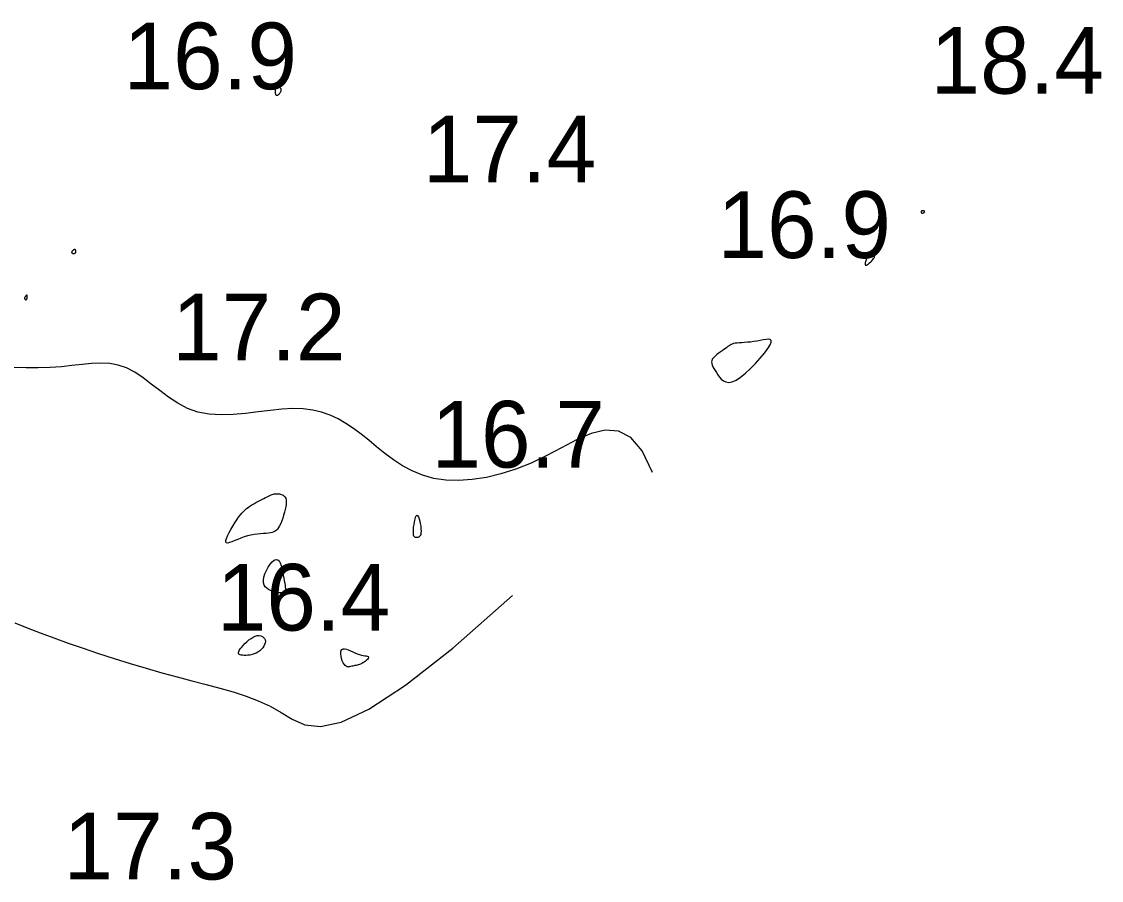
# Model space of a CAD drawing. Extents: x 3040093 to 3056816, y 408076 to 509144.
# Drawn here: x 3045566.4 to 3045647.4, y 433759.6 to 433824 of the extents above; entities that cross this region are included whole.
import ezdxf

# ---------------------------------------------------------------- set-up
doc = ezdxf.new("R2010")
doc.units = 0
doc.layers.add('V-CHAN-CONT-EL17', color=7, linetype='Continuous')
doc.layers.add('V-TOPO-SOUN-0610', color=7, linetype='Continuous')

msp = doc.modelspace()

# ---------------------------------------------------------------- linework, layer by layer
at = {"layer": 'V-CHAN-CONT-EL17'}
for points in [[(3045585.594, 433818.512), (3045585.634, 433818.526), (3045585.676, 433818.551), (3045585.719, 433818.583), (3045585.76, 433818.621), (3045585.799, 433818.664), (3045585.833, 433818.709), (3045585.861, 433818.754), (3045585.883, 433818.798), (3045585.896, 433818.841), (3045585.903, 433818.882), (3045585.903, 433818.921), (3045585.897, 433818.957), (3045585.884, 433818.991), (3045585.864, 433819.021), (3045585.839, 433819.049), (3045585.809, 433819.073), (3045585.774, 433819.093), (3045585.736, 433819.108), (3045585.697, 433819.119), (3045585.657, 433819.124), (3045585.618, 433819.124), (3045585.581, 433819.117), (3045585.548, 433819.104), (3045585.519, 433819.084), (3045585.495, 433819.057), (3045585.476, 433819.025), (3045585.46, 433818.988), (3045585.449, 433818.946), (3045585.441, 433818.901), (3045585.436, 433818.853), (3045585.435, 433818.803), (3045585.437, 433818.752), (3045585.442, 433818.701), (3045585.451, 433818.653), (3045585.463, 433818.608), (3045585.48, 433818.57), (3045585.501, 433818.539), (3045585.527, 433818.518), (3045585.558, 433818.509)], [(3045633.912, 433809.712), (3045633.922, 433809.698), (3045633.935, 433809.686), (3045633.95, 433809.675), (3045633.966, 433809.666), (3045633.984, 433809.661), (3045634.003, 433809.659), (3045634.023, 433809.66), (3045634.043, 433809.666), (3045634.063, 433809.676), (3045634.082, 433809.688), (3045634.1, 433809.703), (3045634.116, 433809.718), (3045634.13, 433809.734), (3045634.142, 433809.75), (3045634.151, 433809.765), (3045634.155, 433809.778), (3045634.157, 433809.79), (3045634.155, 433809.8), (3045634.15, 433809.809), (3045634.141, 433809.816), (3045634.131, 433809.822), (3045634.117, 433809.828), (3045634.101, 433809.833), (3045634.083, 433809.837), (3045634.063, 433809.84), (3045634.043, 433809.843), (3045634.021, 433809.844), (3045634, 433809.844), (3045633.98, 433809.842), (3045633.961, 433809.838), (3045633.944, 433809.832), (3045633.93, 433809.823), (3045633.918, 433809.813), (3045633.909, 433809.801), (3045633.902, 433809.787), (3045633.898, 433809.773), (3045633.897, 433809.758), (3045633.899, 433809.743), (3045633.904, 433809.727)], [(3045570.216, 433806.663), (3045570.242, 433806.653), (3045570.271, 433806.646), (3045570.304, 433806.641), (3045570.338, 433806.64), (3045570.371, 433806.642), (3045570.402, 433806.647), (3045570.429, 433806.654), (3045570.451, 433806.664), (3045570.468, 433806.676), (3045570.48, 433806.691), (3045570.489, 433806.708), (3045570.495, 433806.726), (3045570.498, 433806.746), (3045570.499, 433806.767), (3045570.499, 433806.79), (3045570.498, 433806.813), (3045570.495, 433806.836), (3045570.491, 433806.858), (3045570.486, 433806.879), (3045570.478, 433806.898), (3045570.469, 433806.914), (3045570.456, 433806.926), (3045570.441, 433806.934), (3045570.423, 433806.937), (3045570.402, 433806.935), (3045570.38, 433806.929), (3045570.356, 433806.919), (3045570.331, 433806.905), (3045570.306, 433806.889), (3045570.281, 433806.87), (3045570.258, 433806.85), (3045570.237, 433806.827), (3045570.217, 433806.804), (3045570.202, 433806.78), (3045570.19, 433806.756), (3045570.183, 433806.734), (3045570.181, 433806.712), (3045570.186, 433806.693), (3045570.197, 433806.677)], [(3045629.768, 433806.167), (3045629.739, 433806.089), (3045629.715, 433806.009), (3045629.697, 433805.932), (3045629.69, 433805.864), (3045629.694, 433805.808), (3045629.714, 433805.771), (3045629.75, 433805.758), (3045629.804, 433805.771), (3045629.874, 433805.808), (3045629.953, 433805.864), (3045630.037, 433805.934), (3045630.121, 433806.013), (3045630.201, 433806.095), (3045630.272, 433806.176), (3045630.329, 433806.251), (3045630.367, 433806.316), (3045630.39, 433806.371), (3045630.397, 433806.416), (3045630.393, 433806.452), (3045630.379, 433806.481), (3045630.358, 433806.503), (3045630.332, 433806.518), (3045630.303, 433806.529), (3045630.273, 433806.534), (3045630.242, 433806.536), (3045630.211, 433806.534), (3045630.18, 433806.529), (3045630.149, 433806.522), (3045630.117, 433806.512), (3045630.086, 433806.501), (3045630.054, 433806.488), (3045630.023, 433806.475), (3045629.991, 433806.459), (3045629.959, 433806.44), (3045629.927, 433806.415), (3045629.896, 433806.384), (3045629.864, 433806.346), (3045629.832, 433806.297), (3045629.8, 433806.238)], [(3045566.767, 433803.164), (3045566.781, 433803.171), (3045566.793, 433803.183), (3045566.805, 433803.199), (3045566.815, 433803.219), (3045566.824, 433803.242), (3045566.832, 433803.269), (3045566.839, 433803.299), (3045566.845, 433803.331), (3045566.849, 433803.364), (3045566.852, 433803.397), (3045566.853, 433803.428), (3045566.852, 433803.457), (3045566.849, 433803.482), (3045566.843, 433803.502), (3045566.835, 433803.515), (3045566.825, 433803.52), (3045566.812, 433803.518), (3045566.797, 433803.511), (3045566.781, 433803.499), (3045566.764, 433803.483), (3045566.746, 433803.464), (3045566.729, 433803.444), (3045566.713, 433803.423), (3045566.697, 433803.403), (3045566.683, 433803.384), (3045566.671, 433803.364), (3045566.661, 433803.345), (3045566.654, 433803.326), (3045566.649, 433803.307), (3045566.648, 433803.288), (3045566.65, 433803.269), (3045566.656, 433803.249), (3045566.665, 433803.23), (3045566.676, 433803.212), (3045566.69, 433803.196), (3045566.705, 433803.182), (3045566.721, 433803.171), (3045566.737, 433803.164), (3045566.752, 433803.161)], [(3045620.355, 433797.36), (3045620.725, 433797.658), (3045621.106, 433798.01), (3045621.482, 433798.393), (3045621.833, 433798.784), (3045622.143, 433799.161), (3045622.393, 433799.501), (3045622.565, 433799.78), (3045622.647, 433799.982), (3045622.646, 433800.112), (3045622.574, 433800.184), (3045622.443, 433800.207), (3045622.265, 433800.196), (3045622.053, 433800.16), (3045621.82, 433800.112), (3045621.576, 433800.065), (3045621.334, 433800.027), (3045621.096, 433799.998), (3045620.867, 433799.977), (3045620.65, 433799.961), (3045620.446, 433799.947), (3045620.259, 433799.935), (3045620.093, 433799.92), (3045619.949, 433799.902), (3045619.829, 433799.878), (3045619.729, 433799.847), (3045619.643, 433799.81), (3045619.566, 433799.765), (3045619.491, 433799.713), (3045619.412, 433799.654), (3045619.324, 433799.586), (3045619.222, 433799.511), (3045619.1, 433799.427), (3045618.964, 433799.336), (3045618.821, 433799.238), (3045618.678, 433799.136), (3045618.541, 433799.031), (3045618.417, 433798.923), (3045618.314, 433798.814), (3045618.237, 433798.706), (3045618.193, 433798.598), (3045618.179, 433798.49), (3045618.193, 433798.379), (3045618.23, 433798.263), (3045618.287, 433798.14), (3045618.362, 433798.009), (3045618.449, 433797.866), (3045618.547, 433797.709), (3045618.654, 433797.541), (3045618.772, 433797.371), (3045618.907, 433797.215), (3045619.064, 433797.086), (3045619.248, 433797), (3045619.465, 433796.971), (3045619.719, 433797.012), (3045620.015, 433797.139)], [(3045581.743, 433785.102), (3045581.79, 433785.267), (3045581.875, 433785.469), (3045581.988, 433785.698), (3045582.123, 433785.942), (3045582.271, 433786.19), (3045582.422, 433786.43), (3045582.569, 433786.652), (3045582.706, 433786.846), (3045582.833, 433787.014), (3045582.954, 433787.16), (3045583.07, 433787.287), (3045583.186, 433787.399), (3045583.304, 433787.5), (3045583.427, 433787.593), (3045583.558, 433787.683), (3045583.698, 433787.772), (3045583.847, 433787.86), (3045584, 433787.947), (3045584.155, 433788.032), (3045584.308, 433788.113), (3045584.458, 433788.189), (3045584.599, 433788.261), (3045584.731, 433788.327), (3045584.849, 433788.386), (3045584.956, 433788.438), (3045585.053, 433788.484), (3045585.143, 433788.523), (3045585.226, 433788.555), (3045585.305, 433788.581), (3045585.381, 433788.6), (3045585.457, 433788.613), (3045585.535, 433788.62), (3045585.612, 433788.621), (3045585.69, 433788.616), (3045585.766, 433788.605), (3045585.841, 433788.588), (3045585.913, 433788.566), (3045585.982, 433788.538), (3045586.046, 433788.505), (3045586.106, 433788.467), (3045586.159, 433788.42), (3045586.204, 433788.363), (3045586.241, 433788.292), (3045586.267, 433788.205), (3045586.281, 433788.098), (3045586.282, 433787.97), (3045586.269, 433787.817), (3045586.241, 433787.638), (3045586.199, 433787.439), (3045586.145, 433787.226), (3045586.082, 433787.008), (3045586.013, 433786.791), (3045585.938, 433786.582), (3045585.861, 433786.39), (3045585.783, 433786.22), (3045585.705, 433786.078), (3045585.627, 433785.964), (3045585.543, 433785.873), (3045585.452, 433785.803), (3045585.349, 433785.749), (3045585.232, 433785.709), (3045585.098, 433785.68), (3045584.942, 433785.657), (3045584.764, 433785.639), (3045584.566, 433785.621), (3045584.35, 433785.602), (3045584.12, 433785.577), (3045583.879, 433785.546), (3045583.631, 433785.504), (3045583.379, 433785.449), (3045583.126, 433785.378), (3045582.876, 433785.291), (3045582.635, 433785.194), (3045582.41, 433785.099), (3045582.207, 433785.015), (3045582.032, 433784.952), (3045581.892, 433784.92), (3045581.793, 433784.928), (3045581.742, 433784.986)], [(3045595.818, 433785.913), (3045595.834, 433786.11), (3045595.86, 433786.317), (3045595.894, 433786.519), (3045595.935, 433786.703), (3045595.981, 433786.854), (3045596.031, 433786.957), (3045596.084, 433786.999), (3045596.138, 433786.97), (3045596.192, 433786.879), (3045596.244, 433786.74), (3045596.29, 433786.567), (3045596.33, 433786.374), (3045596.361, 433786.174), (3045596.381, 433785.981), (3045596.388, 433785.81), (3045596.38, 433785.671), (3045596.36, 433785.563), (3045596.329, 433785.481), (3045596.289, 433785.423), (3045596.242, 433785.383), (3045596.19, 433785.358), (3045596.136, 433785.343), (3045596.082, 433785.335), (3045596.029, 433785.33), (3045595.979, 433785.332), (3045595.933, 433785.346), (3045595.893, 433785.375), (3045595.859, 433785.425), (3045595.834, 433785.499), (3045595.817, 433785.603), (3045595.812, 433785.74)], [(3045585.24, 433781.312), (3045585.09, 433781.367), (3045584.946, 433781.436), (3045584.814, 433781.523), (3045584.702, 433781.632), (3045584.617, 433781.766), (3045584.567, 433781.929), (3045584.559, 433782.124), (3045584.598, 433782.353), (3045584.678, 433782.603), (3045584.79, 433782.858), (3045584.925, 433783.105), (3045585.075, 433783.327), (3045585.23, 433783.509), (3045585.382, 433783.636), (3045585.522, 433783.693), (3045585.643, 433783.669), (3045585.745, 433783.574), (3045585.831, 433783.421), (3045585.903, 433783.225), (3045585.963, 433782.999), (3045586.014, 433782.757), (3045586.057, 433782.515), (3045586.096, 433782.284), (3045586.131, 433782.077), (3045586.162, 433781.896), (3045586.187, 433781.738), (3045586.204, 433781.603), (3045586.212, 433781.488), (3045586.208, 433781.394), (3045586.191, 433781.318), (3045586.16, 433781.26), (3045586.112, 433781.217), (3045586.049, 433781.189), (3045585.97, 433781.175), (3045585.878, 433781.173), (3045585.773, 433781.183), (3045585.656, 433781.202), (3045585.527, 433781.231), (3045585.388, 433781.268)], [(3045582.922, 433777.093), (3045583.039, 433777.23), (3045583.173, 433777.373), (3045583.32, 433777.515), (3045583.475, 433777.649), (3045583.636, 433777.768), (3045583.797, 433777.865), (3045583.955, 433777.935), (3045584.106, 433777.97), (3045584.246, 433777.975), (3045584.373, 433777.951), (3045584.484, 433777.903), (3045584.575, 433777.834), (3045584.645, 433777.747), (3045584.691, 433777.647), (3045584.709, 433777.536), (3045584.697, 433777.419), (3045584.658, 433777.298), (3045584.595, 433777.177), (3045584.509, 433777.057), (3045584.406, 433776.943), (3045584.286, 433776.838), (3045584.154, 433776.743), (3045584.012, 433776.663), (3045583.863, 433776.599), (3045583.711, 433776.551), (3045583.558, 433776.517), (3045583.408, 433776.496), (3045583.265, 433776.486), (3045583.131, 433776.486), (3045583.01, 433776.494), (3045582.906, 433776.509), (3045582.82, 433776.53), (3045582.754, 433776.557), (3045582.71, 433776.594), (3045582.687, 433776.641), (3045582.686, 433776.7), (3045582.709, 433776.773), (3045582.756, 433776.862), (3045582.827, 433776.969)], [(3045590.542, 433776.983), (3045590.653, 433776.983), (3045590.785, 433776.951), (3045590.934, 433776.896), (3045591.095, 433776.826), (3045591.263, 433776.749), (3045591.434, 433776.672), (3045591.602, 433776.605), (3045591.763, 433776.554), (3045591.914, 433776.516), (3045592.052, 433776.487), (3045592.174, 433776.465), (3045592.277, 433776.445), (3045592.358, 433776.423), (3045592.414, 433776.396), (3045592.443, 433776.36), (3045592.441, 433776.311), (3045592.414, 433776.253), (3045592.365, 433776.188), (3045592.298, 433776.12), (3045592.217, 433776.05), (3045592.128, 433775.984), (3045592.034, 433775.923), (3045591.94, 433775.87), (3045591.85, 433775.829), (3045591.763, 433775.797), (3045591.678, 433775.773), (3045591.595, 433775.754), (3045591.514, 433775.739), (3045591.433, 433775.725), (3045591.351, 433775.711), (3045591.269, 433775.693), (3045591.185, 433775.672), (3045591.099, 433775.65), (3045591.014, 433775.635), (3045590.929, 433775.629), (3045590.846, 433775.64), (3045590.764, 433775.672), (3045590.686, 433775.729), (3045590.611, 433775.819), (3045590.541, 433775.942), (3045590.479, 433776.091), (3045590.428, 433776.256), (3045590.391, 433776.426), (3045590.373, 433776.59), (3045590.375, 433776.738), (3045590.402, 433776.859), (3045590.457, 433776.943)]]:
    msp.add_lwpolyline(points, close=True, dxfattribs=at)
for points in [[(3045613.743, 433790.214), (3045612.986, 433791.838), (3045612.135, 433792.84), (3045611.202, 433793.321), (3045610.2, 433793.383), (3045609.144, 433793.125), (3045608.046, 433792.65), (3045606.92, 433792.059), (3045605.779, 433791.452), (3045604.636, 433790.914), (3045603.501, 433790.465), (3045602.382, 433790.107), (3045601.287, 433789.842), (3045600.227, 433789.672), (3045599.209, 433789.602), (3045598.243, 433789.632), (3045597.336, 433789.766), (3045596.496, 433790.003), (3045595.717, 433790.327), (3045594.991, 433790.72), (3045594.311, 433791.165), (3045593.668, 433791.642), (3045593.056, 433792.134), (3045592.466, 433792.622), (3045591.89, 433793.087), (3045591.32, 433793.514), (3045590.749, 433793.896), (3045590.166, 433794.229), (3045589.564, 433794.508), (3045588.933, 433794.73), (3045588.264, 433794.89), (3045587.55, 433794.984), (3045586.78, 433795.008), (3045585.95, 433794.962), (3045585.072, 433794.868), (3045584.161, 433794.751), (3045583.233, 433794.638), (3045582.303, 433794.554), (3045581.386, 433794.526), (3045580.499, 433794.578), (3045579.657, 433794.738), (3045578.872, 433795.021), (3045578.138, 433795.405), (3045577.446, 433795.859), (3045576.787, 433796.35), (3045576.153, 433796.847), (3045575.534, 433797.318), (3045574.921, 433797.731), (3045574.306, 433798.055), (3045573.679, 433798.265), (3045573.036, 433798.376), (3045572.371, 433798.406), (3045571.68, 433798.377), (3045570.959, 433798.31), (3045570.203, 433798.225), (3045569.407, 433798.143), (3045568.567, 433798.085), (3045567.681, 433798.065), (3045566.768, 433798.07), (3045565.847, 433798.079)], [(3045565.919, 433778.943), (3045566.849, 433778.56), (3045567.817, 433778.183), (3045568.835, 433777.804), (3045569.91, 433777.418), (3045571.033, 433777.029), (3045572.192, 433776.641), (3045573.375, 433776.258), (3045574.569, 433775.885), (3045575.76, 433775.526), (3045576.938, 433775.187), (3045578.088, 433774.871), (3045579.2, 433774.581), (3045580.273, 433774.305), (3045581.307, 433774.031), (3045582.303, 433773.745), (3045583.259, 433773.433), (3045584.178, 433773.084), (3045585.059, 433772.682), (3045585.903, 433772.215), (3045586.733, 433771.702), (3045587.665, 433771.29), (3045588.84, 433771.158), (3045590.398, 433771.487), (3045592.477, 433772.455), (3045595.218, 433774.243), (3045598.76, 433777.029), (3045603.243, 433780.994)]]:
    msp.add_lwpolyline(points, dxfattribs=at)

# ---------------------------------------------------------------- texts
at = {"layer": 'V-TOPO-SOUN-0610'}
for s, p in [('16.9 ', (3045574.073, 433818.96)), ('18.4 ', (3045634.603, 433818.63)), ('17.4 ', (3045596.513, 433811.97)), ('16.9 ', (3045618.623, 433806.3)), ('17.2 ', (3045577.713, 433798.62)), ('16.7 ', (3045597.163, 433790.58)), ('16.4 ', (3045581.063, 433778.35)), ('17.3 ', (3045569.573, 433759.68))]:
    msp.add_text(s, height=5, dxfattribs=at).set_placement(p)

doc.saveas('drawing.dxf')
